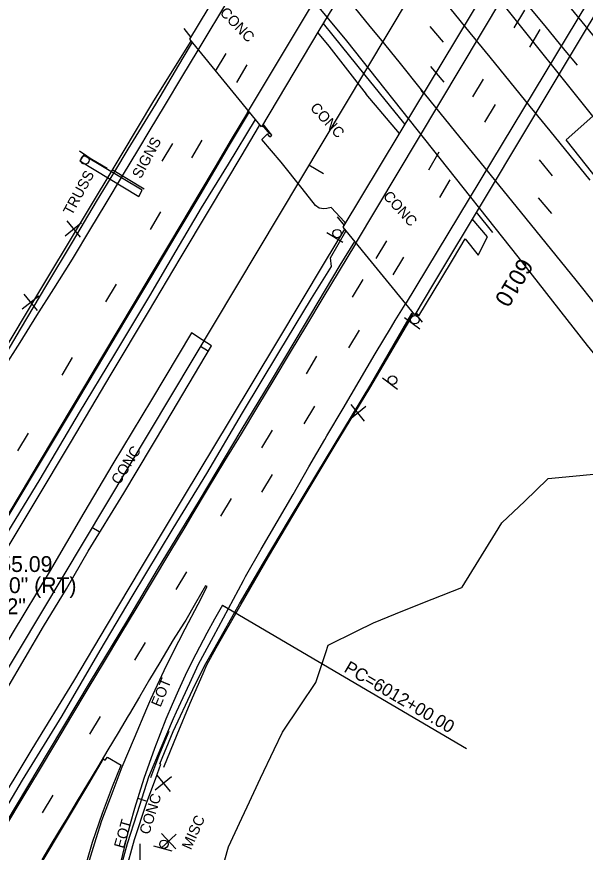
# Model space of a CAD drawing. Extents: x 2132221 to 2141942, y 535736 to 547298.
# Drawn here: x 2137871.9 to 2138140.9, y 540212.3 to 540608 of the extents above; entities that cross this region are included whole.
import ezdxf

# ---------------------------------------------------------------- set-up
doc = ezdxf.new("R2010")
doc.units = 0
for name, color, linetype in [('RD_EX_BldgApp', 7, 'Continuous'), ('RD_EX_BldgApp_txCode', 7, 'Continuous'), ('RD_EX_Bridge', 7, 'Continuous'), ('RD_EX_Bridge_txCode', 7, 'Continuous'), ('RD_EX_Conc', 7, 'Continuous'), ('RD_EX_Conc_txCode', 7, 'Continuous'), ('RD_EX_GuardRail', 7, 'Continuous'), ('RD_EX_Misc', 7, 'Continuous'), ('RD_EX_Misc_txCode', 7, 'Continuous'), ('RD_EX_Road', 7, 'Continuous'), ('RD_EX_VEG', 7, 'Continuous'), ('RD_HC_Cl', 7, 'Continuous'), ('RD_HC_Data', 7, 'Continuous'), ('RD_HC_Data_Tic', 7, 'Continuous'), ('RD_HC_TX_Sta50', 7, 'Continuous')]:
    doc.layers.add(name, color=color, linetype=linetype)

msp = doc.modelspace()

# ---------------------------------------------------------------- linework, layer by layer
at = {"layer": 'RD_EX_BldgApp'}
for p, q in [((2137909.01, 540539.24), (2137901.55, 540544.27)), ((2137903.88, 540542.53), (2137914.65, 540536.16)), ((2137916.99, 540535.54), (2137932.15, 540526.39)), ((2138018.53, 540505.82), (2138026.24, 540501.19)), ((2138055.38, 540465.47), (2138062.68, 540460.2)), ((2138044.86, 540436.9), (2138052.06, 540431.5)), ((2137936.64, 540215.36), (2137945.3, 540212.9))]:
    msp.add_line(p, q, dxfattribs=at)
msp.add_lwpolyline([(2137901.66, 540539.63), (2137929.58, 540522.88), (2137931.2, 540525.87), (2137903.41, 540542.42)], close=True, dxfattribs=at)
for centre in [(2137904.13, 540540.09), (2138023.44, 540505.23), (2138060.23, 540464.47), (2138049.68, 540435.81), (2137941.54, 540216.07)]:
    msp.add_circle(centre, 2, dxfattribs=at)
at = {"layer": 'RD_EX_Bridge'}
for p, q in [((2137950.86, 540602.31), (2137954.28, 540598.13)), ((2137991.59, 540552.43), (2137988.13, 540556.59)), ((2138023.42, 540513.2), (2138026.8, 540509.05)), ((2138063.9, 540463.34), (2138060.53, 540467.46))]:
    msp.add_line(p, q, dxfattribs=at)
for points in [[(2137953.8, 540597.33), (2137980.31, 540641.29), (2138035.33, 540732.91), (2138089.95, 540824.31), (2138117.06, 540869.51), (2138150.9, 540828.27), (2138124.68, 540784.61), (2138092.38, 540730.7), (2138062.06, 540680.27), (2138036.85, 540637.89), (2138014.74, 540601.36), (2137987.7, 540555.87)], [(2138026.38, 540508.35), (2138052.81, 540552.29), (2138066.16, 540574.64), (2138094.39, 540621.7), (2138107.74, 540643.97), (2138127.43, 540676.68), (2138147.16, 540709.72), (2138166.66, 540742.2), (2138189.69, 540780.49), (2138223.49, 540739.59), (2138196.62, 540694.61), (2138174.28, 540657.34), (2138152.06, 540620.19), (2138133.77, 540589.58), (2138111.58, 540552.61), (2138092.98, 540521.56), (2138068.99, 540481.55), (2138060.16, 540466.85)]]:
    msp.add_lwpolyline(points, close=True, dxfattribs=at)
at = {"layer": 'RD_EX_Conc'}
for p, q in [((2138027.48, 540510.18), (2138026.93, 540510.87)), ((2138062.09, 540466.27), (2138060.79, 540467.91))]:
    msp.add_line(p, q, dxfattribs=at)
for points in [[(2138014.21, 540600.47), (2138019.47, 540593.95), (2138037.2, 540571.29)], [(2137845.23, 540415.08), (2137852.97, 540426.39), (2137863.52, 540443.06), (2137873.68, 540459.95), (2137886.1, 540480.97), (2137898.32, 540501.25), (2137909.63, 540520.42), (2137918.31, 540534.7), (2137924.61, 540545.23), (2137937.63, 540566.61), (2137950.64, 540588.54), (2137955, 540595.86)], [(2138053.04, 540552.67), (2138037.2, 540571.29)], [(2137934.87, 540483.57), (2137947.78, 540505.37), (2137958.64, 540523.51), (2137972.51, 540547.12), (2137979.2, 540558.19), (2137981.93, 540562.94)], [(2137991.66, 540551.04), (2137992.58, 540551.93), (2137988.42, 540557.07)], [(2138026.93, 540510.87), (2138020.69, 540517.63), (2138018.64, 540517.18), (2138017.11, 540516.98), (2138014.97, 540517.27), (2138013.16, 540518.56), (2138006.88, 540526.54), (2137996.94, 540539.02), (2137987.77, 540549.76), (2137990.54, 540552.47)], [(2137991.66, 540551.04), (2137990.54, 540552.47)], [(2138062.09, 540466.27), (2138072.46, 540483.5), (2138078.52, 540493.39), (2138084.02, 540502.83), (2138090.15, 540495.11), (2138094.64, 540503.78), (2138087.41, 540512.27)], [(2137713.64, 539970.82), (2137732.77, 540002.73), (2137754.54, 540038.88), (2137774.87, 540072.65), (2137796.35, 540108.71), (2137811.65, 540134.17), (2137831.33, 540166.97), (2137849.27, 540196.71), (2137866.87, 540226.25), (2137887.32, 540260.59), (2137906.74, 540293.11), (2137923.94, 540321.54), (2137938.5, 540346.14), (2137958.31, 540378.88), (2137978.1, 540412.05), (2137991.96, 540434.88), (2138004.02, 540455.28), (2138024.93, 540490.24), (2138031.92, 540501.55)], [(2137649.49, 540005.97), (2137662.45, 540027.48), (2137674.6, 540048.13), (2137696.78, 540085.11), (2137709.65, 540106.68), (2137726.77, 540135.32), (2137744.66, 540165.37), (2137769.19, 540206.25), (2137796.76, 540252.44), (2137813.78, 540280.79), (2137845.52, 540334.11), (2137868.31, 540372.02), (2137887.39, 540403.97), (2137896.81, 540419.76), (2137909.57, 540441.16), (2137923.45, 540464.49), (2137934.87, 540483.57)], [(2137965.71, 540309.41), (2137977.28, 540329.99), (2137988.61, 540349.35), (2138000.92, 540370.02), (2138013.85, 540391.43), (2138039.38, 540433.84), (2138059.32, 540467.88)], [(2137811.74, 540195.42), (2137826.56, 540221.45), (2137837.74, 540240.83), (2137867.26, 540289.45), (2137884.5, 540319.17), (2137895.41, 540337.08), (2137905.71, 540354.8), (2137922.53, 540382.31), (2137942.39, 540415.65), (2137964.1, 540452.08), (2137959.64, 540454.95), (2137954.53, 540458.3), (2137935.65, 540426.47), (2137917.38, 540396.18), (2137903.64, 540373.04), (2137887.15, 540344.96), (2137869.69, 540315.85), (2137854.49, 540289.77), (2137842.08, 540268.76), (2137826.22, 540242.98), (2137804.59, 540206.43)], [(2137939.99, 540253.96), (2137939.52, 540254.13), (2137945.9, 540269.39), (2137955.22, 540289.41), (2137960.76, 540300.49), (2137965.71, 540309.41)], [(2137730.9, 539952.54), (2137740.51, 539968.7), (2137753.87, 539990.79), (2137775.16, 540026.49), (2137795.95, 540060.93), (2137811.6, 540087.21), (2137834.36, 540125.19), (2137852.58, 540155.59), (2137868.21, 540181.51), (2137883.39, 540206.97), (2137905.94, 540244.68), (2137912.93, 540256.45), (2137913.77, 540255.93), (2137914.8, 540257.33), (2137921.22, 540253.56)], [(2137905.01, 540207.8), (2137907.76, 540217.04), (2137912.4, 540230.82), (2137917.26, 540243.4), (2137921.22, 540253.56)], [(2137915.7, 540043.68), (2137913.31, 540054.94), (2137911.99, 540063.87), (2137911.15, 540071.63), (2137910.32, 540083.65), (2137910.15, 540094.05), (2137910.27, 540106.45), (2137910.75, 540117.55), (2137911.3, 540126.81), (2137911.67, 540132.71), (2137912.26, 540137.8), (2137914.8, 540159.64), (2137917.2, 540173.8), (2137919.61, 540186.63), (2137923.34, 540202.85), (2137927.57, 540218.29), (2137933.22, 540235.54), (2137937.62, 540247.43), (2137939.99, 540253.96)]]:
    msp.add_lwpolyline(points, dxfattribs=at)
at = {"layer": 'RD_EX_GuardRail'}
for points in [[(2137938.25, 540829.52), (2137947.77, 540817.93), (2137957.28, 540806.33), (2137966.8, 540794.74), (2137976.32, 540783.15), (2137985.84, 540771.55), (2137995.35, 540759.96), (2137997.51, 540757.33), (2138006.86, 540745.6), (2138016.21, 540733.87), (2138025.56, 540722.14), (2138034.91, 540710.41), (2138044.25, 540698.68), (2138053.6, 540686.95), (2138062.95, 540675.22), (2138072.3, 540663.49), (2138073.97, 540661.4), (2138083.52, 540649.83), (2138093.07, 540638.27), (2138102.62, 540626.7), (2138112.17, 540615.13), (2138121.72, 540603.57), (2138131.28, 540592), (2138137.06, 540584.99)], [(2138016.79, 540604.75), (2138021.46, 540599.04), (2138036.61, 540580.34), (2138054.9, 540557.63), (2138055.53, 540556.85)], [(2137954.27, 540596.34), (2137936.61, 540568.19), (2137921.63, 540543.06), (2137902.42, 540510.95), (2137881.71, 540476.5), (2137864.2, 540447.18), (2137854.16, 540430.98), (2137847.85, 540421.26), (2137844.23, 540416.23), (2137838, 540408.31), (2137832.4, 540401.71), (2137826.6, 540395.51), (2137823.74, 540393.5), (2137820.87, 540392.37)], [(2137821.26, 540269.71), (2137821.03, 540271.78), (2137821.97, 540275.47), (2137822.87, 540278), (2137825.34, 540283.1), (2137829.5, 540291.44), (2137833.69, 540299.56), (2137843.35, 540315.92), (2137854.29, 540334.2), (2137866.42, 540354.59), (2137880.58, 540378.23), (2137897.27, 540406.1), (2137916.55, 540438.64), (2137934.26, 540468.16), (2137949.27, 540493.47), (2137963.1, 540516.64), (2137978.1, 540541.76), (2137986.66, 540556.36)], [(2138089.28, 540515.39), (2138097.06, 540505.84)], [(2138026.93, 540507.42), (2138017.3, 540491.35), (2137995.21, 540454.51), (2137972.37, 540416.46), (2137951.1, 540381.12), (2137930.81, 540347.08), (2137914.64, 540320.17), (2137898.67, 540293.37), (2137879.07, 540261.11), (2137870.51, 540246.95), (2137867.16, 540241.51), (2137860.72, 540231.27), (2137849.74, 540213.81)], [(2137941.43, 540252.49), (2137947.83, 540268), (2137954, 540282.89), (2137960.01, 540297), (2137961.87, 540301), (2137966.23, 540309.14), (2137978.01, 540329.79), (2137990.94, 540352.23), (2138005.53, 540376.68), (2138022.56, 540405.1), (2138038.89, 540432.08), (2138059.5, 540466.93)]]:
    msp.add_lwpolyline(points, dxfattribs=at)
at = {"layer": 'RD_EX_Misc'}
for p, q in [((2138121.34, 540865.79), (2137957.56, 540592.11)), ((2138032.12, 540500.47), (2138244.29, 540855.51)), ((2137981.08, 540562.65), (2138145.31, 540836.26)), ((2138107.25, 540602.7), (2138112.25, 540611.09)), ((2138067.28, 540603.35), (2138073.58, 540595.83)), ((2138114.62, 540593.48), (2138119.61, 540601.86)), ((2137965.93, 540582.19), (2137970.92, 540590.58)), ((2137975.98, 540576.8), (2137980.98, 540585.18)), ((2138067.66, 540584.41), (2138073.96, 540576.89)), ((2138087.67, 540569.98), (2138092.67, 540578.37)), ((2138093.42, 540557.94), (2138098.42, 540566.33)), ((2137954.69, 540541.06), (2137959.68, 540549.45)), ((2137940.74, 540539.57), (2137945.74, 540547.96)), ((2138066.82, 540535.52), (2138071.81, 540543.9)), ((2138118.99, 540540.15), (2138125.29, 540532.63)), ((2138072.02, 540522.34), (2138077.01, 540530.72)), ((2138118.64, 540522.25), (2138124.93, 540514.73)), ((2137935.14, 540507.24), (2137940.13, 540515.63)), ((2137894.78, 540504.22), (2137902.55, 540510.51)), ((2137895.52, 540511.25), (2137901.81, 540503.48)), ((2138041.98, 540493.47), (2138046.97, 540501.86)), ((2138050.04, 540485.73), (2138055.03, 540494.12)), ((2138030.82, 540475.14), (2138035.81, 540483.53)), ((2137914.06, 540472.87), (2137919.05, 540481.25)), ((2137874.51, 540469.56), (2137882.28, 540475.85)), ((2137875.25, 540476.59), (2137881.54, 540468.82)), ((2138029.06, 540451.16), (2138034.06, 540459.54)), ((2137893.3, 540438.25), (2137898.3, 540446.64)), ((2138008.94, 540438.78), (2138013.93, 540447.16)), ((2138007.91, 540415.18), (2138012.9, 540423.56)), ((2138029.29, 540417.21), (2138037.06, 540423.51)), ((2138030.03, 540424.24), (2138036.32, 540416.47)), ((2137872.42, 540402.32), (2137877.42, 540410.7)), ((2137987.91, 540403.74), (2137992.91, 540412.12)), ((2137987.91, 540382.77), (2137992.91, 540391.15)), ((2137968.43, 540371.39), (2137973.42, 540379.77)), ((2137947.33, 540336.69), (2137952.33, 540345.07)), ((2137927.77, 540303.16), (2137932.76, 540311.54)), ((2137906.45, 540268.24), (2137911.45, 540276.62)), ((2137938.11, 540248.85), (2137944.4, 540241.08)), ((2137937.37, 540241.82), (2137945.14, 540248.12)), ((2137884.07, 540230.92), (2137889.07, 540239.31)), ((2137940.02, 540214.11), (2137947.38, 540220.89)), ((2137940.31, 540221.18), (2137947.09, 540213.82)), ((2137930.34, 540206.21), (2137930.34, 540216.21))]:
    msp.add_line(p, q, dxfattribs=at)
for points in [[(2138276.15, 540838.41), (2138192.92, 540699.37), (2138055.7, 540471.61)], [(2138029.42, 540614.97), (2138038.91, 540603.35), (2138043.77, 540597.41), (2138053.22, 540585.77), (2138062.68, 540574.12), (2138072.13, 540562.48), (2138081.59, 540550.83), (2138091.04, 540539.19), (2138100.5, 540527.54), (2138108.06, 540518.23), (2138117.49, 540506.56), (2138126.92, 540494.89), (2138136.34, 540483.22), (2138145.77, 540471.55)], [(2138076.73, 540612), (2138086.2, 540600.37), (2138095.67, 540588.74), (2138105.15, 540577.11), (2138114.62, 540565.48), (2138124.1, 540553.86), (2138133.57, 540542.23), (2138143.04, 540530.6)], [(2137957.56, 540592.11), (2137949.83, 540579.26), (2137942.1, 540566.41), (2137934.37, 540553.55), (2137929.45, 540545.39), (2137921.72, 540532.53), (2137913.99, 540519.68), (2137906.26, 540506.83), (2137898.53, 540493.97), (2137897.24, 540491.83), (2137889.25, 540479.14), (2137881.26, 540466.44), (2137873.27, 540453.75), (2137865.28, 540441.05)], [(2138063.03, 540573.14), (2138064.31, 540571.54)], [(2137981.08, 540562.65), (2137973.41, 540549.76), (2137965.74, 540536.87), (2137958.07, 540523.98), (2137950.4, 540511.09), (2137942.73, 540498.19), (2137935.06, 540485.3), (2137927.39, 540472.41), (2137919.72, 540459.52), (2137912.05, 540446.63), (2137904.38, 540433.74), (2137896.71, 540420.85), (2137889.74, 540409.14), (2137882.07, 540396.25), (2137874.4, 540383.36), (2137866.73, 540370.47)], [(2138032.12, 540500.47), (2138024.39, 540487.62), (2138016.66, 540474.76), (2138008.92, 540461.91), (2138001.19, 540449.06), (2137993.45, 540436.21), (2137985.72, 540423.35), (2137977.99, 540410.5), (2137970.25, 540397.65), (2137962.52, 540384.8), (2137954.78, 540371.94), (2137951.82, 540367.01), (2137944.11, 540354.15), (2137936.4, 540341.28), (2137928.69, 540328.41), (2137920.99, 540315.54), (2137913.28, 540302.67), (2137905.57, 540289.8), (2137897.86, 540276.94), (2137890.15, 540264.07), (2137882.45, 540251.2), (2137874.74, 540238.33), (2137867.03, 540225.46)], [(2137920.53, 540202.68), (2137924.32, 540216.38), (2137928.89, 540230.66), (2137933.46, 540244.95), (2137934.44, 540248), (2137940.27, 540261.82), (2137946.1, 540275.64), (2137947.43, 540278.79), (2137953.77, 540292.38), (2137957.92, 540301.27), (2137964.99, 540314.5), (2137972.06, 540327.73), (2137979.13, 540340.96), (2137980.1, 540342.78), (2137987.6, 540355.77), (2137995.09, 540368.76), (2138002.59, 540381.76), (2138010.08, 540394.75), (2138017.58, 540407.74), (2138018.61, 540409.53), (2138026.25, 540422.44), (2138033.89, 540435.35), (2138041.53, 540448.26), (2138049.18, 540461.16), (2138050.88, 540464.04), (2138055.7, 540471.61)], [(2137905.01, 540204.47), (2137909.47, 540218.79), (2137912.13, 540227.35), (2137917.47, 540241.37), (2137921.77, 540252.68), (2137927.61, 540266.5), (2137933.44, 540280.32), (2137935.29, 540284.71), (2137941.68, 540298.28), (2137945.52, 540306.45), (2137951.59, 540318.06), (2137957.66, 540329.68), (2137962.03, 540338.06), (2137961.24, 540338.42), (2137956.52, 540330.28), (2137951.82, 540322.16), (2137950.99, 540320.73), (2137945.96, 540312.8), (2137944.3, 540310.19), (2137939.54, 540302.11), (2137934.77, 540294.03), (2137930, 540285.94), (2137925.23, 540277.86), (2137924.66, 540276.9), (2137919.83, 540268.85), (2137915, 540260.81), (2137910.17, 540252.76), (2137905.34, 540244.71), (2137900.51, 540236.67), (2137895.68, 540228.62), (2137893.36, 540224.77), (2137888.53, 540216.72), (2137883.7, 540208.67)], [(2137935.39, 540247.74), (2137939.64, 540259.02), (2137943.94, 540269.61)]]:
    msp.add_lwpolyline(points, dxfattribs=at)
at = {"layer": 'RD_EX_Road'}
for points in [[(2138244.22, 540344.28), (2138234.7, 540354.22), (2138208.65, 540383.09), (2138201.29, 540391.25), (2138195.4, 540387.67), (2138180.18, 540405.51), (2138141.91, 540452.23), (2138109.14, 540494.28), (2138028.11, 540596.49), (2137968.46, 540668.53), (2137916.16, 540729.78), (2137901.22, 540749.03), (2137907.3, 540753.74), (2137893.66, 540774.07), (2137875.34, 540800.95)], [(2138029.88, 540775.65), (2138095.4, 540696.57), (2138151.16, 540628.9), (2138177.28, 540598.73), (2138190, 540608.42), (2138214.79, 540578.17), (2138185.33, 540555.75), (2138177.74, 540548.69), (2138150.47, 540526.11), (2138131.79, 540549.6), (2138144.53, 540560.85), (2138101.97, 540613.85)], [(2137947.3, 540497.01), (2137959.36, 540517.51), (2137972.12, 540538.2), (2137984.92, 540559.28)], [(2137708.24, 539968.78), (2137729.97, 540004.8), (2137746.05, 540031.45), (2137761.55, 540057.62), (2137777.94, 540084.75), (2137793.66, 540111.15), (2137814.43, 540145.61), (2137839.9, 540188.06), (2137856.65, 540216.1), (2137874.61, 540246.34), (2137893.3, 540276.84), (2137911.41, 540307.83), (2137926.54, 540333.4), (2137945.86, 540365.55), (2137961.76, 540391.71), (2137978.67, 540420.33), (2137995.96, 540448.98), (2138011.33, 540474.56), (2138020.84, 540489.65), (2138020.33, 540493.72), (2138027.65, 540506.32)], [(2137653.2, 540005.1), (2137666.51, 540027.31), (2137678.04, 540046.22), (2137687.25, 540061.86), (2137707.01, 540094.79), (2137722.29, 540120.21), (2137741.2, 540151.98), (2137757.04, 540178.82), (2137772.71, 540205.25), (2137790.44, 540234.79), (2137804.98, 540258.92), (2137821.09, 540285.79), (2137836.96, 540312.17), (2137852.69, 540338.96), (2137869.39, 540366.66), (2137883.03, 540388.95), (2137901.6, 540420.49), (2137917.74, 540447.35), (2137934.82, 540475.85), (2137947.3, 540497.01)], [(2137965.71, 540309.41), (2137977.28, 540329.99), (2137988.61, 540349.35), (2138000.92, 540370.02), (2138013.85, 540391.43), (2138039.38, 540433.84), (2138058.82, 540467.33)]]:
    msp.add_lwpolyline(points, dxfattribs=at)
at = {"layer": 'RD_EX_VEG'}
msp.add_lwpolyline([(2137968.98, 540203.65), (2137972.01, 540214.83), (2137978.38, 540228.4), (2137980.89, 540233.73), (2137987.27, 540247.31), (2137993.64, 540260.89), (2137997.55, 540269.2), (2138005.92, 540281.64), (2138013.34, 540292.66), (2138018.08, 540306.89), (2138019.22, 540310.29), (2138032.64, 540316.99), (2138040.63, 540320.97), (2138054.55, 540326.54), (2138068.48, 540332.12), (2138082.41, 540337.69), (2138082.7, 540337.8), (2138090.55, 540350.58), (2138098.41, 540363.36), (2138101.39, 540368.2), (2138112.22, 540378.58), (2138123.06, 540388.95), (2138123.36, 540389.24), (2138138.29, 540390.67), (2138152.81, 540392.05)], dxfattribs=at)
at = {"layer": 'RD_HC_Cl'}
for p, q in [((2139719.79, 543396.28), (2136851.48, 538600.7)), ((2136971.61, 542041.65), (2141699.63, 536226.46))]:
    msp.add_line(p, q, dxfattribs=at)
msp.add_arc((2138337.99, 540112.74), 427.61, 149.586, 181.7808, dxfattribs=at)
at = {"layer": 'RD_HC_Data'}
msp.add_line((2137969.23, 540329.21), (2138084.62, 540261.48), dxfattribs=at)
at = {"layer": 'RD_HC_Data_Tic'}
for p, q in [((2138010.1, 540537.81), (2138016.96, 540533.71)), ((2137958.77, 540451.99), (2137962.2, 540449.94)), ((2137907.44, 540366.17), (2137910.87, 540364.12)), ((2137969.23, 540329.21), (2137972.68, 540327.19)), ((2137929.1, 540237.87), (2137932.93, 540236.7))]:
    msp.add_line(p, q, dxfattribs=at)

# ---------------------------------------------------------------- texts
at = {"layer": 'RD_EX_BldgApp_txCode'}
for s, p in [('SIGNS', (2137930.53, 540530.87)), ('TRUSS', (2137897.94, 540513.49))]:
    msp.add_text(s, height=5, rotation=61.5422, dxfattribs=at).set_placement(p)
at = {"layer": 'RD_EX_Bridge_txCode'}
for rotation, p in [(314.0169, (2137967.63, 540609.58)), (312.4535, (2138044.86, 540522.69))]:
    msp.add_text('CONC', height=5, rotation=rotation, dxfattribs=at).set_placement(p)
at = {"layer": 'RD_EX_Conc_txCode'}
for rotation, p in [(312.6539, (2138010.37, 540564.51)), (58.014, (2137920.45, 540385.96)), (72.6233, (2137934.52, 540220.31))]:
    msp.add_text('CONC', height=5, rotation=rotation, dxfattribs=at).set_placement(p)
at = {"layer": 'RD_EX_Misc_txCode'}
for s, rotation, p in [('EOT', 67.5732, (2137939.87, 540280.68)), ('MISC', 66.0583, (2137954.3, 540213.1)), ('EOT', 74.0599, (2137922.56, 540213.76))]:
    msp.add_text(s, height=5, rotation=rotation, dxfattribs=at).set_placement(p)
at = {"layer": 'RD_HC_Data'}
for s, p in [('P.I. = 6012+55.09', (2137809, 540345)), ('    = 24%%d 47\' 20" (RT)', (2137809, 540335)), ('D = 11%%d 58\' 52"', (2137809, 540325))]:
    msp.add_text(s, height=7.5, dxfattribs=at).set_placement(p)
msp.add_text('PC=6012+00.00', height=6, rotation=329.586, dxfattribs=at).set_placement((2138026.3, 540298.03))
at = {"layer": 'RD_HC_TX_Sta50'}
msp.add_text('6010', height=8, rotation=239.1157, dxfattribs=at).set_placement((2138109.92, 540494.31))

doc.saveas('drawing.dxf')
